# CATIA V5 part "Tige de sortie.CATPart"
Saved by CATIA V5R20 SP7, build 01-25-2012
Part number: Tige de sortie
Bounding box of the stored display mesh (mm): x -20.994 to 20.994, y -20.994 to 20.994, z -105 to 0
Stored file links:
  F:\Travaux\Modélisations\CFAO_2011\MMS\MMS_GR1\AA_OK\bmadec\Catia\Tige de sortie.CATPart
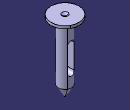
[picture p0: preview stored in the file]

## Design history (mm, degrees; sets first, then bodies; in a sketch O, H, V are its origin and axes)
Body1 (main body)
  Sketch1 on yz-plane, origin (0, 0, 0), H (0, 1, 0), V (0, 0, 1)
    line L1 (0, 0) -> (21, 0)
    line L2 (21, 0) -> (21, -4)
    line L3 (21, -4) -> (9.75, -4)
    line L4 (9.75, -4) -> (9.75, -90)
    line L5 (9.75, -90) -> (1, -105)
    line L6 (1, -105) -> (0, -105)
    point P6 (0, -105)
    line L7 (0, -105) -> (0, 0)
    distance L7 L4 = 9.75
    length L7 = 105
    length L6 = 1
    length L1 = 21
    distance L3 L1 = 4
    length L5 V = 15
    horizontal: L1 H, L3 H, L6 H
    vertical: L2 V, L4 V, L7 V
    coincidence: P6 V
  Shaft1: profile Sketch1, axis Sketch1.L7, angle 360
  Sketch2 on zx-plane, origin (0, 0, 0), H (-1, 0, 0), V (0, 0, 1)
    line L1 (4.875, -34) -> (4.875, -70)
    arc A1 centre (0, -70) radius 4.875 from (4.875, -70) to (-4.875, -70) cw
    point P3 (0, -70)
    line L2 (-4.875, -70) -> (-4.875, -34)
    arc A2 centre (0, -34) radius 4.875 from (-4.875, -34) to (4.875, -34) cw
    point P6 (0, -34)
    reference projected line E1 (1, -105) -> (-1, -105) from edge [face of Shaft1 from Sketch1.L5 | face of Shaft1 from Sketch1.L6]
    reference projected line E2 (21, -4) -> (-21, -4) from edge [face of Shaft1 from Sketch1.L2 | face of Shaft1 from Sketch1.L3]
    distance L1 L2 = 9.75
    distance P3 E1 = 35
    distance P6 E2 = 30
    vertical: L1 V
    tangency: A1 L1, L2 A1, A2 L1, A2 L2
    symmetry: L1 L2 V
  Pocket1: profile Sketch2, direction (0, -1, 0), up to face of Shaft1 from Sketch1.L4, opposite side up to face of Shaft1 from Sketch1.L4
  Sketch3 on {plane type Tangent, Support face of Shaft1 from Sketch1.L4, RefPoint {point type OnSurface, Support face of Shaft1 from Sketch1.L4, RefPoint {point stored without definition}, Length 0, Direction (0, 0, 1000)}}, origin (-0.2099, -9.7477, -78.5791), H (0.9998, -0.0215, 0), V (0, 0, -1)
    point P1 (0.2099, -8.5791)
    reference intersected line E1 through (0.2099, 0) direction (0, 1) from yz-plane
    reference projected line E2 (-1, 26.4209) -> (1, 26.4209) from edge [face of Shaft1 from Sketch1.L5 | face of Shaft1 from Sketch1.L6]
    distance P1 E2 = 35
    coincidence: P1 E1
  Hole1: placed by Sketch3, at (0, -9.75, -70) direction (0, 1, 0), diameter 15, depth 6
  Sketch4 on zx-plane, origin (0, 0, 0), H (-1, 0, 0), V (0, 0, 1)
    arc A1 centre (0, 4) radius 6 from (4.4721, 0) to (0, -2) cw
    point P1 (0, 4)
    point P2 (4.4721, 0)
    point P3 (0, -2)
    line L1 (0, -2) -> (0, 0)
    line L2 (4.4721, 0) -> (0, 0)
    radius A1 = 6
    length L1 = 2
    coincidence: P2 H, P3 V, P1 V
    vertical: L1 V
    horizontal: L2 H
  Groove1: profile Sketch4, axis axis of face of Shaft1 from Sketch1.L4, angle 360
